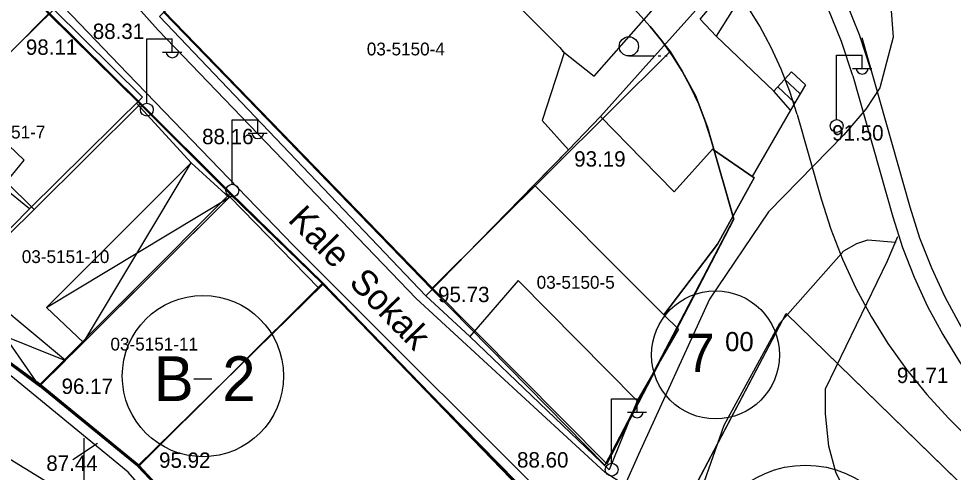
# Model space of a CAD drawing. Extents: x 412225 to 413380, y 4456471 to 4457189.
# Drawn here: x 412722.7 to 412795.7, y 4456530.5 to 4456566 of the extents above; entities that cross this region are included whole.
import ezdxf

# ---------------------------------------------------------------- set-up
doc = ezdxf.new("R2010")
doc.units = 0
for name, color, linetype in [('0_HALİHAZIR', 7, 'Continuous'), ('0_KADASTRO', 7, 'Continuous'), ('Level 27', 7, 'Continuous'), ('Level 29', 7, 'Continuous'), ('Level 34', 7, 'Continuous'), ('Level 54', 7, 'Continuous'), ('Level 62', 7, 'Continuous'), ('SEMBOL', 7, 'Continuous')]:
    doc.layers.add(name, color=color, linetype=linetype)

msp = doc.modelspace()

# ---------------------------------------------------------------- linework, layer by layer
at = {"layer": '0_HALİHAZIR'}
for p, q in [((412732.731, 4456559.391), (412732.731, 4456564.391)), ((412732.731, 4456564.391), (412734.731, 4456564.391)), ((412734.731, 4456563.391), (412734.731, 4456564.391)), ((412733.971, 4456563.351), (412735.471, 4456563.351)), ((412770.388, 4456563.06), (412772.388, 4456563.06)), ((412772.688, 4456563.06), (412772.888, 4456563.06)), ((412773.188, 4456563.06), (412773.388, 4456563.06)), ((412786.615, 4456558.119), (412786.615, 4456563.119)), ((412786.615, 4456563.119), (412788.615, 4456563.119)), ((412788.615, 4456562.119), (412788.615, 4456563.119)), ((412787.855, 4456562.079), (412789.355, 4456562.079)), ((412783.353, 4456559.404), (412782.015, 4456560.648)), ((412783.77, 4456560.108), (412782.554, 4456561.239)), ((412739.41, 4456553.073), (412739.41, 4456558.073)), ((412739.41, 4456558.073), (412741.41, 4456558.073)), ((412741.41, 4456557.073), (412741.41, 4456558.073)), ((412740.65, 4456557.033), (412742.15, 4456557.033)), ((412727.795, 4456540.678), (412736.213, 4456554.708)), ((412724.906, 4456543.422), (412739.176, 4456552.012)), ((412724.369, 4456537.267), (412718.313, 4456545.985)), ((412716.228, 4456543.349), (412726.396, 4456539.285)), ((412769.041, 4456531.281), (412769.041, 4456536.281)), ((412769.041, 4456536.281), (412771.041, 4456536.281)), ((412771.041, 4456535.281), (412771.041, 4456536.281)), ((412770.281, 4456535.241), (412771.781, 4456535.241)), ((412727.857, 4456528.21), (412727.857, 4456533.21)), ((412726.967, 4456531.56), (412728.897, 4456532.83))]:
    msp.add_line(p, q, dxfattribs=at)
for points in [[(412771.155, 4456531.928), (412770.074, 4456529.55), (412768.538, 4456530.535), (412753.789, 4456544.124), (412733.621, 4456565.065), (412711.563, 4456589.67)], [(412730.288, 4456511.351), (412733.501, 4456525.022), (412733.532, 4456525.717), (412733.431, 4456527.104), (412733.312, 4456527.823), (412732.876, 4456528.74), (412731.294, 4456530.548), (412713.777, 4456544.91), (412694.121, 4456564.827), (412684.433, 4456576.054), (412683.291, 4456577.693), (412682.561, 4456579.136), (412682.187, 4456580.49), (412682.082, 4456582.122), (412683.379, 4456588.605)], [(412760.718, 4456481.134), (412766.566, 4456497.487), (412769.861, 4456508.564), (412769.885, 4456509.805), (412769.597, 4456511.831), (412769.038, 4456513.675), (412767.797, 4456521.368), (412767.644, 4456523.561), (412767.321, 4456525.177), (412744.171, 4456548.282), (412731.237, 4456561.704), (412716.304, 4456577.23), (412706.034, 4456587.937)], [(412777.252, 4456582.983), (412789.967, 4456569.43), (412790.445, 4456568.655), (412790.831, 4456567.258), (412791.043, 4456564.517), (412789.998, 4456560.575), (412788.912, 4456558.913), (412787.182, 4456556.891), (412781.284, 4456550.886), (412776.679, 4456544.077), (412771.155, 4456531.928)], [(412771.548, 4456565.873), (412779.318, 4456574.73), (412781.058, 4456572.738)], [(412707.279, 4456512.579), (412681.07, 4456539.882), (412666.691, 4456554.375), (412671.456, 4456564.508), (412679.518, 4456573.325), (412696.363, 4456556.411), (412720.214, 4456532.704), (412727.998, 4456527.942), (412728.331, 4456527.58), (412728.486, 4456527.256), (412723.948, 4456509.495), (412717.044, 4456483.009), (412717.044, 4456483.009), (412706.118, 4456485.723), (412679.506, 4456493.262)], [(412771.503, 4456562.049), (412781.058, 4456572.738)], [(412765.192, 4456563.469), (412767.69, 4456561.476), (412771.548, 4456565.873)], [(412777.197, 4456564.605), (412781.704, 4456560.308)], [(412768.171, 4456558.321), (412771.503, 4456562.049)], [(412731.937, 4456559.362), (412736.213, 4456554.708)], [(412783.006, 4456558.82), (412780.011, 4456553.649)], [(412771.207, 4456536.414), (412771.044, 4456536.129), (412768.842, 4456530.74), (412757.977, 4456541.15), (412754.532, 4456544.32), (412763, 4456553.007), (412765.666, 4456555.742), (412768.171, 4456558.321), (412771.422, 4456555.01)], [(412771.422, 4456555.01), (412768.171, 4456558.321), (412765.666, 4456555.742), (412763, 4456553.007), (412771.302, 4456544.667)], [(412771.422, 4456555.01), (412773.925, 4456552.461), (412776.935, 4456555.771), (412780.177, 4456553.535), (412777.311, 4456548.365), (412773.127, 4456542.833), (412774.264, 4456541.738), (412771.207, 4456536.414)], [(412771.302, 4456544.667), (412773.127, 4456542.833), (412777.311, 4456548.365), (412780.177, 4456553.535), (412776.935, 4456555.771), (412773.925, 4456552.461), (412771.422, 4456555.01)], [(412771.207, 4456536.414), (412771.044, 4456536.129), (412761.747, 4456545.528), (412757.977, 4456541.15), (412754.532, 4456544.32), (412763, 4456553.007), (412771.302, 4456544.667)], [(412723.569, 4456551.126), (412718.421, 4456545.896)], [(412788.322, 4456527.236), (412787.516, 4456528.598), (412786.564, 4456530.568), (412786.014, 4456532.591), (412785.741, 4456535.121), (412785.761, 4456537.054), (412790.595, 4456547.066), (412791.393, 4456548.95)], [(412798.79, 4456480.697), (412798.501, 4456480.927), (412794.838, 4456487.712), (412789.316, 4456494.381), (412774.007, 4456510.82), (412772.951, 4456512.262), (412772.981, 4456512.692), (412775.14, 4456525.848), (412775.775, 4456528.362), (412777.841, 4456534.237), (412782.172, 4456542.189), (412787.185, 4456547.843), (412788.196, 4456548.418), (412789.064, 4456548.69), (412791.206, 4456548.509), (412791.225, 4456548.5)], [(412771.302, 4456544.667), (412773.127, 4456542.833), (412774.264, 4456541.738), (412771.207, 4456536.414)]]:
    msp.add_lwpolyline(points, dxfattribs=at)
for points in [[(412765, 4456563.724), (412765.325, 4456563.294), (412763.628, 4456558.011), (412765.666, 4456555.742), (412754.532, 4456544.32), (412733.724, 4456566.136), (412747.741, 4456580.387), (412751.774, 4456576.277), (412751.971, 4456576.535), (412761.743, 4456566.984)], [(412710.167, 4456565.795), (412717.023, 4456558.8), (412718.233, 4456559.604), (412725.469, 4456566.698), (412723.946, 4456568.094), (412723.632, 4456567.734), (412720.306, 4456571.165), (412720.934, 4456571.876), (412718.699, 4456574.067)], [(412777.519, 4456567.802), (412778.55, 4456566.71), (412777.197, 4456564.605), (412775.961, 4456565.94)], [(412725.469, 4456566.698), (412732.414, 4456559.831), (412723.569, 4456551.126), (412721.478, 4456552.829), (412723.153, 4456554.923), (412718.233, 4456559.604)], [(412783.093, 4456561.831), (412784.187, 4456560.812), (412783.006, 4456558.82), (412781.704, 4456560.308)], [(412724.906, 4456543.422), (412727.795, 4456540.678), (412739.176, 4456552.012), (412736.213, 4456554.708)], [(412739.235, 4456552.071), (412746.182, 4456544.915), (412732.004, 4456531.025), (412724.369, 4456537.267)], [(412718.313, 4456545.985), (412716.228, 4456543.349), (412724.369, 4456537.267), (412726.396, 4456539.285)], [(412746.477, 4456545.205), (412732.004, 4456531.025), (412734.816, 4456528.062), (412734.814, 4456524.211), (412759.789, 4456513.909), (412765.681, 4456525.656)]]:
    msp.add_lwpolyline(points, close=True, dxfattribs=at)
for centre, radius in [((412770.388, 4456563.81), 0.75), ((412732.742, 4456558.867), 0.5), ((412786.626, 4456557.595), 0.5), ((412739.42, 4456552.549), 0.5), ((412769.052, 4456530.757), 0.5)]:
    msp.add_circle(centre, radius, dxfattribs=at)
for centre in [(412734.731, 4456563.395), (412788.616, 4456562.123), (412741.41, 4456557.077), (412771.041, 4456535.285)]:
    msp.add_arc(centre, 0.474, 184.83843, 355.14641, dxfattribs=at)
at = {"layer": '0_KADASTRO'}
for points in [[(412734.06, 4456566.46), (412752.722, 4456585.141), (412771.088, 4456566.42), (412772.061, 4456565.364), (412773.615, 4456563.41), (412754.98, 4456544.87)], [(412709.631, 4456566.048), (412718.24, 4456573.88), (412725.07, 4456566.36), (412716.668, 4456557.916), (412712.004, 4456562.941), (412710.062, 4456565.484)], [(412716.668, 4456557.916), (412725.07, 4456566.36), (412732.21, 4456559.29), (412723.934, 4456551.069), (412721.715, 4456553.277)], [(412754.98, 4456544.87), (412773.615, 4456563.41), (412774.559, 4456561.863), (412775.583, 4456559.967), (412776.535, 4456557.512), (412778.575, 4456550.321), (412768.502, 4456531.112)], [(412716.08, 4456543.35), (412723.934, 4456551.069), (412732.21, 4456559.29), (412739.23, 4456552.3), (412724.33, 4456537.35)], [(412709.07, 4456550.62), (412716.668, 4456557.916), (412721.715, 4456553.277), (412723.934, 4456551.069), (412716.08, 4456543.35)], [(412724.33, 4456537.35), (412739.23, 4456552.3), (412746.44, 4456545.28), (412732.1, 4456531)], [(412732.1, 4456531), (412746.44, 4456545.28), (412765.58, 4456525.49), (412759.84, 4456513.94), (412758.39, 4456514.32), (412755.16, 4456515.39), (412751.73, 4456516.76), (412745.79, 4456518.44), (412735.04, 4456522.7), (412734.574, 4456522.944), (412734.64, 4456524.25), (412735.27, 4456525.75), (412734.68, 4456528.23)], [(412767.08, 4456513.3), (412782.67, 4456542.96), (412820.53, 4456506.05), (412820.47, 4456501.47), (412803.6, 4456483.36), (412798.26, 4456483.09)]]:
    msp.add_lwpolyline(points, close=True, dxfattribs=at)
at = {"layer": 'Level 27'}
for p, q in [((412725.092, 4456566.462), (412732.232, 4456559.392)), ((412755.002, 4456544.972), (412734.082, 4456566.562)), ((412732.232, 4456559.392), (412739.252, 4456552.402)), ((412739.252, 4456552.402), (412746.462, 4456545.382)), ((412778.578, 4456550.312), (412768.682, 4456531.202)), ((412746.462, 4456545.382), (412765.602, 4456525.592)), ((412768.682, 4456531.202), (412755.002, 4456544.972)), ((412724.352, 4456537.452), (412716.532, 4456543.139)), ((412767.08, 4456513.3), (412782.67, 4456542.96)), ((412732.122, 4456531.102), (412724.352, 4456537.452)), ((412734.702, 4456528.332), (412732.122, 4456531.102))]:
    msp.add_line(p, q, dxfattribs=at)
at = {"layer": 'Level 29'}
for p, q in [((412771.088, 4456566.42), (412772.061, 4456565.364)), ((412772.061, 4456565.364), (412772.966, 4456564.25)), ((412772.966, 4456564.25), (412773.8, 4456563.081)), ((412773.8, 4456563.081), (412774.559, 4456561.863)), ((412774.559, 4456561.863), (412775.241, 4456560.6)), ((412775.241, 4456560.6), (412775.843, 4456559.297)), ((412775.843, 4456559.297), (412776.362, 4456557.958)), ((412776.362, 4456557.958), (412776.797, 4456556.59)), ((412776.797, 4456556.59), (412778.578, 4456550.312)), ((412782.67, 4456542.96), (412820.53, 4456506.05))]:
    msp.add_line(p, q, dxfattribs=at)
at = {"layer": 'Level 34'}
msp.add_lwpolyline([(412705.467, 4456595.951), (412710.523, 4456590.729), (412734.082, 4456566.562), (412755.002, 4456544.972), (412768.682, 4456531.202), (412778.578, 4456550.312), (412776.797, 4456556.59), (412776.362, 4456557.958), (412775.843, 4456559.297), (412775.241, 4456560.6), (412774.559, 4456561.863), (412773.8, 4456563.081), (412772.966, 4456564.25), (412772.061, 4456565.364), (412771.088, 4456566.42)], dxfattribs=at)
msp.add_lwpolyline([(412767.08, 4456513.3), (412782.67, 4456542.96), (412820.53, 4456506.05), (412820.47, 4456501.47), (412803.6, 4456483.36), (412798.26, 4456483.09)], close=True, dxfattribs=at)
at = {"layer": 'Level 54'}
for points in [[(412697.966, 4456594.392), (412718.262, 4456573.982), (412725.092, 4456566.462), (412732.232, 4456559.392), (412739.252, 4456552.402), (412746.462, 4456545.382), (412765.602, 4456525.592), (412757.942, 4456510.178), (412766.508, 4456501.131), (412762.962, 4456491.562), (412760.062, 4456483.992), (412759.039, 4456481.227)], [(412724.145, 4456481.63), (412732.752, 4456515.572), (412735.292, 4456525.852), (412734.702, 4456528.332), (412732.122, 4456531.102), (412724.352, 4456537.452), (412716.532, 4456543.139), (412711.003, 4456548.816), (412679.159, 4456581.279), (412679.8, 4456583.189), (412680.419, 4456585.105), (412681.015, 4456587.029), (412681.59, 4456588.96), (412681.782, 4456589.635)]]:
    msp.add_lwpolyline(points, dxfattribs=at)
at = {"layer": 'Level 62'}
for p, q in [((412788.583, 4456564.505), (412792.34, 4456551.267)), ((412787.875, 4456561.508), (412791, 4456550.493)), ((412783.531, 4456558.501), (412785.401, 4456551.909)), ((412795.358, 4456534.784), (412849.032, 4456480.187))]:
    msp.add_line(p, q, dxfattribs=at)
for points in [[(412789.318, 4456561.917), (412788.412, 4456564.712), (412787.304, 4456567.434), (412785.999, 4456570.066), (412784.504, 4456572.596), (412782.828, 4456575.009), (412780.979, 4456577.293), (412778.967, 4456579.434), (412776.804, 4456581.423)], [(412787.875, 4456561.508), (412787.003, 4456564.198), (412785.936, 4456566.817), (412784.68, 4456569.351), (412783.242, 4456571.786), (412781.628, 4456574.109), (412779.848, 4456576.307), (412777.912, 4456578.368), (412775.83, 4456580.282)], [(412783.531, 4456558.501), (412782.964, 4456560.285), (412782.287, 4456562.031), (412781.502, 4456563.731), (412780.612, 4456565.379), (412779.622, 4456566.968), (412778.535, 4456568.492), (412777.354, 4456569.945), (412776.085, 4456571.322)], [(412785.401, 4456551.909), (412786.159, 4456549.524), (412787.064, 4456547.192), (412788.114, 4456544.921), (412789.303, 4456542.72), (412790.627, 4456540.598), (412792.082, 4456538.563), (412793.661, 4456536.622), (412795.358, 4456534.784)], [(412792.34, 4456551.267), (412793.103, 4456548.868), (412794.016, 4456546.522), (412795.074, 4456544.239), (412796.273, 4456542.026), (412797.61, 4456539.893), (412799.078, 4456537.848), (412800.671, 4456535.9), (412802.384, 4456534.056)], [(412791, 4456550.493), (412791.758, 4456548.108), (412792.663, 4456545.776), (412793.713, 4456543.505), (412794.902, 4456541.304), (412796.226, 4456539.182), (412797.681, 4456537.146), (412799.26, 4456535.206), (412800.957, 4456533.368)]]:
    msp.add_lwpolyline(points, dxfattribs=at)
at = {"layer": 'SEMBOL'}
msp.add_line((412736.425, 4456537.857), (412737.825, 4456537.857), dxfattribs=at)
for centre, radius in [((412777.159, 4456539.713), 5), ((412737.125, 4456538.064), 6.3), ((412784.185, 4456523.003), 8.1)]:
    msp.add_circle(centre, radius, dxfattribs=at)

# ---------------------------------------------------------------- texts
at = {"layer": '0_HALİHAZIR'}
for s, height, p in [('88.31', 1.2, (412728.52, 4456564.387)), ('98.11', 1.2, (412723.294, 4456563.15)), ('03-5150-4', 1, (412749.922, 4456563.105)), ('03-5151-7', 1, (412718.719, 4456556.616)), ('88.16', 1.2, (412737.06, 4456556.17)), ('91.50', 1.2, (412786.268, 4456556.456)), ('93.19', 1.2, (412766.119, 4456554.419)), ('03-5151-10', 1, (412722.975, 4456546.89)), ('03-5150-5', 1, (412763.189, 4456544.883)), ('95.73', 1.2, (412755.489, 4456543.837)), ('03-5151-11', 1, (412729.9, 4456540.059)), ('91.71', 1.2, (412791.324, 4456537.517)), ('96.17', 1.2, (412726.084, 4456536.666)), ('88.60', 1.2, (412761.656, 4456530.92)), ('87.44', 1.2, (412724.891, 4456530.66)), ('95.92', 1.2, (412733.699, 4456530.896))]:
    msp.add_text(s, height=height, dxfattribs=at).set_placement(p)
msp.add_text('Kale  Sokak', height=2, rotation=314.20575, dxfattribs=at).set_placement((412743.682, 4456550.193))
at = {"layer": '0_KADASTRO'}
for s, p in [('03-5150-4', (412749.922, 4456563.105)), ('03-5151-7', (412718.719, 4456556.616)), ('03-5151-10', (412722.975, 4456546.89)), ('03-5150-5', (412763.189, 4456544.883)), ('03-5151-11', (412729.9, 4456540.059))]:
    msp.add_text(s, height=1, dxfattribs=at).set_placement(p)
at = {"layer": 'SEMBOL'}
for s, height, p in [('7', 3, (412774.862, 4456538.373)), ('00', 1.5, (412777.908, 4456540.003)), ('B', 3.5, (412733.281, 4456536.107)), ('2', 3.5, (412738.633, 4456536.107))]:
    msp.add_text(s, height=height, dxfattribs=at).set_placement(p)

doc.saveas('drawing.dxf')
